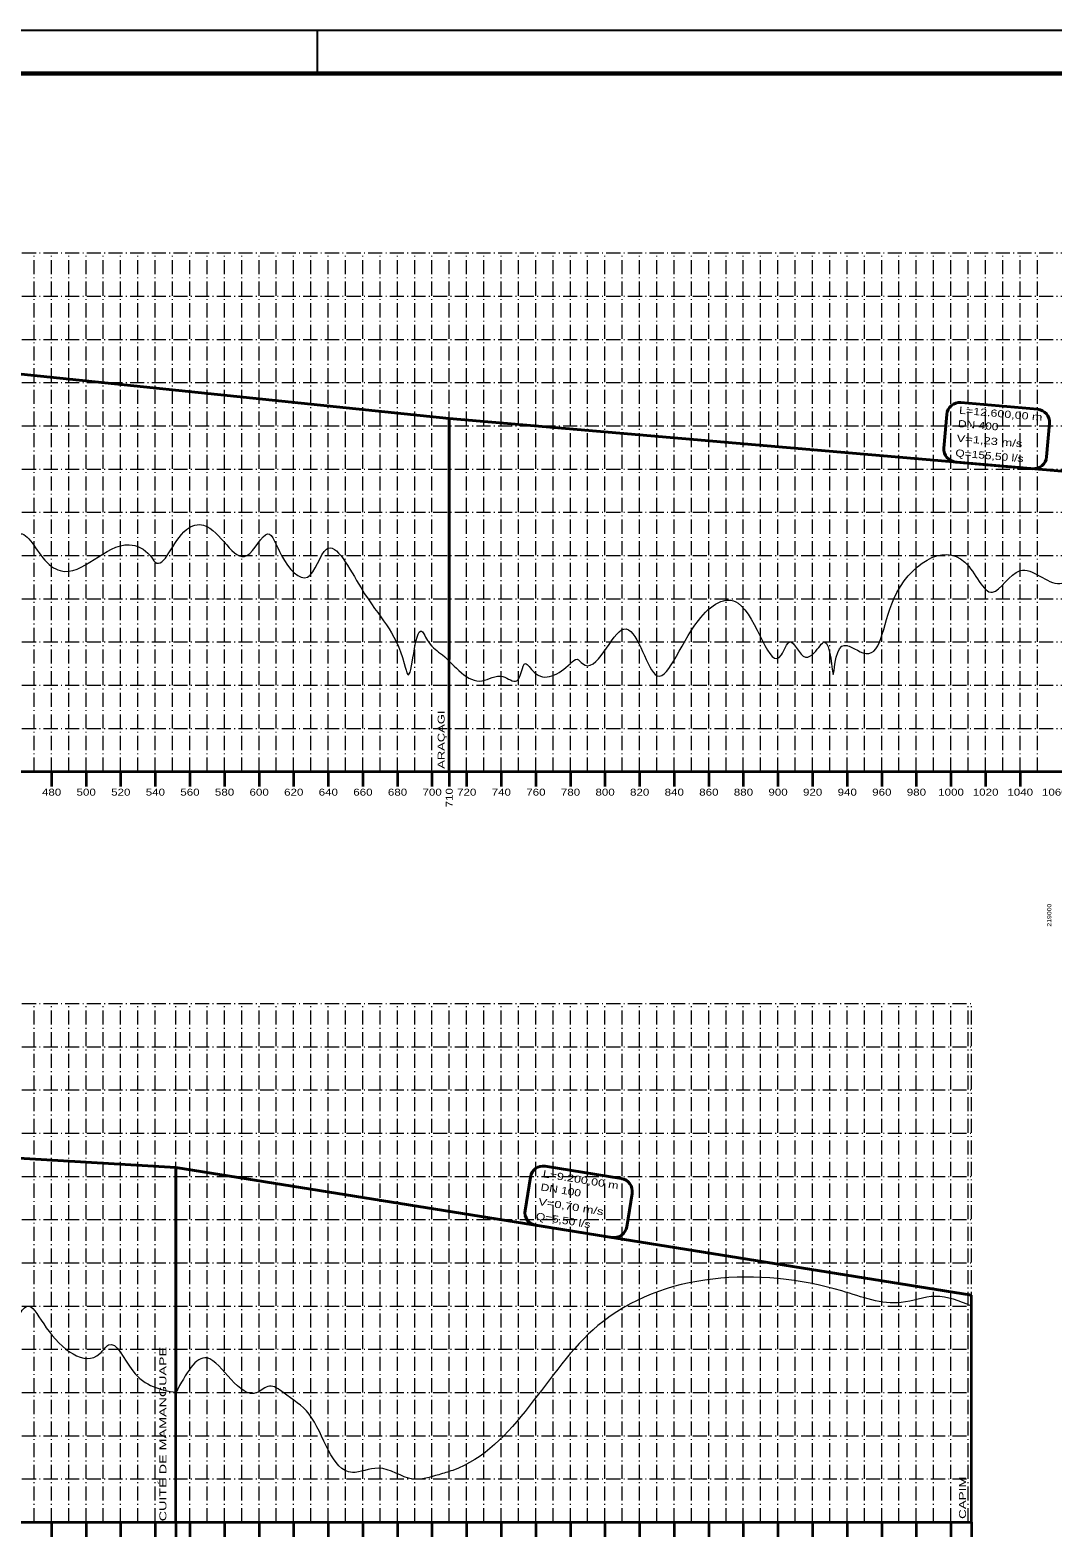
# Model space of a CAD drawing. Extents: x 0 to 1682, y 0 to 1188.
# Drawn here: x 479 to 952, y 490 to 1188 of the extents above; entities that cross this region are included whole.
import ezdxf
from ezdxf.enums import TextEntityAlignment as Align

# ---------------------------------------------------------------- set-up
doc = ezdxf.new("R2010")
doc.units = 0
doc.header["$LTSCALE"] = 1.3
doc.linetypes.add('DOT_DASHED', pattern=[7.7, 5, -1.2, 0.3, -1.2])
for name, color, linetype, lineweight in [('1', 7, 'DOT_DASHED', 13), ('55', 7, 'Continuous', 13), ('56', 7, 'Continuous', 13), ('62', 7, 'Continuous', 13), ('63', 7, 'Continuous', 25), ('9', 7, 'Continuous', 40)]:
    doc.layers.add(name, color=color, linetype=linetype, lineweight=lineweight)
doc.layers.add('24', color=7, linetype='Continuous')

msp = doc.modelspace()

# ---------------------------------------------------------------- linework, layer by layer
at = {"layer": '1'}
for p, q in [((104.775, 1084.796), (1296.775, 1084.796)), ((480.775, 844.796), (480.775, 1084.796)), ((488.775, 844.796), (488.775, 1084.796)), ((496.775, 844.796), (496.775, 1084.796)), ((504.775, 844.796), (504.775, 1084.796)), ((512.775, 844.796), (512.775, 1084.796)), ((520.775, 844.796), (520.775, 1084.796)), ((528.775, 844.796), (528.775, 1084.796)), ((536.775, 844.796), (536.775, 1084.796)), ((544.775, 844.796), (544.775, 1084.796)), ((552.775, 844.796), (552.775, 1084.796)), ((560.775, 844.796), (560.775, 1084.796)), ((568.775, 844.796), (568.775, 1084.796)), ((576.775, 844.796), (576.775, 1084.796)), ((584.775, 844.796), (584.775, 1084.796)), ((592.775, 844.796), (592.775, 1084.796)), ((600.775, 844.796), (600.775, 1084.796)), ((608.775, 844.796), (608.775, 1084.796)), ((616.775, 844.796), (616.775, 1084.796)), ((624.775, 844.796), (624.775, 1084.796)), ((632.775, 844.796), (632.775, 1084.796)), ((640.775, 844.796), (640.775, 1084.796)), ((648.775, 844.796), (648.775, 1084.796)), ((656.775, 844.796), (656.775, 1084.796)), ((664.775, 844.796), (664.775, 1084.796)), ((672.775, 844.796), (672.775, 1084.796)), ((680.775, 844.796), (680.775, 1084.796)), ((688.775, 844.796), (688.775, 1084.796)), ((696.775, 844.796), (696.775, 1084.796)), ((704.775, 844.796), (704.775, 1084.796)), ((712.775, 844.796), (712.775, 1084.796)), ((720.775, 844.796), (720.775, 1084.796)), ((728.775, 844.796), (728.775, 1084.796)), ((736.775, 844.796), (736.775, 1084.796)), ((744.775, 844.796), (744.775, 1084.796)), ((752.775, 844.796), (752.775, 1084.796)), ((760.775, 844.796), (760.775, 1084.796)), ((768.775, 844.796), (768.775, 1084.796)), ((776.775, 844.796), (776.775, 1084.796)), ((784.775, 844.796), (784.775, 1084.796)), ((792.775, 844.796), (792.775, 1084.796)), ((800.775, 844.796), (800.775, 1084.796)), ((808.775, 844.796), (808.775, 1084.796)), ((816.775, 844.796), (816.775, 1084.796)), ((824.775, 844.796), (824.775, 1084.796)), ((832.775, 844.796), (832.775, 1084.796)), ((840.775, 844.796), (840.775, 1084.796)), ((848.775, 844.796), (848.775, 1084.796)), ((856.775, 844.796), (856.775, 1084.796)), ((864.775, 844.796), (864.775, 1084.796)), ((872.775, 844.796), (872.775, 1084.796)), ((880.775, 844.796), (880.775, 1084.796)), ((888.775, 844.796), (888.775, 1084.796)), ((896.775, 844.796), (896.775, 1084.796)), ((904.775, 844.796), (904.775, 1084.796)), ((912.775, 844.796), (912.775, 1084.796)), ((920.775, 844.796), (920.775, 1084.796)), ((928.775, 844.796), (928.775, 1084.796)), ((936.775, 844.796), (936.775, 1084.796)), ((944.775, 844.796), (944.775, 1084.796)), ((104.775, 1064.796), (1296.775, 1064.796)), ((104.775, 1044.796), (1296.775, 1044.796)), ((104.775, 1024.796), (1296.775, 1024.796)), ((104.775, 1004.796), (1296.775, 1004.796)), ((104.775, 984.796), (1296.775, 984.796)), ((104.775, 964.796), (1296.775, 964.796)), ((104.775, 944.796), (1296.775, 944.796)), ((104.775, 924.796), (1296.775, 924.796)), ((104.775, 904.796), (1296.775, 904.796)), ((104.775, 884.796), (1296.775, 884.796)), ((104.775, 864.796), (1296.775, 864.796)), ((104.775, 737.538), (914.356, 737.538)), ((480.775, 497.538), (480.775, 737.538)), ((488.775, 497.538), (488.775, 737.538)), ((496.775, 497.538), (496.775, 737.538)), ((504.775, 497.538), (504.775, 737.538)), ((512.775, 497.538), (512.775, 737.538)), ((520.775, 497.538), (520.775, 737.538)), ((528.775, 497.538), (528.775, 737.538)), ((536.775, 497.538), (536.775, 737.538)), ((546.375, 497.538), (546.375, 737.538)), ((552.775, 497.538), (552.775, 737.538)), ((560.775, 497.538), (560.775, 737.538)), ((568.775, 497.538), (568.775, 737.538)), ((576.775, 497.538), (576.775, 737.538)), ((584.775, 497.538), (584.775, 737.538)), ((592.775, 497.538), (592.775, 737.538)), ((600.775, 497.538), (600.775, 737.538)), ((608.775, 497.538), (608.775, 737.538)), ((616.775, 497.538), (616.775, 737.538)), ((624.775, 497.538), (624.775, 737.538)), ((632.775, 497.538), (632.775, 737.538)), ((640.775, 497.538), (640.775, 737.538)), ((648.775, 497.538), (648.775, 737.538)), ((656.775, 497.538), (656.775, 737.538)), ((664.775, 497.538), (664.775, 737.538)), ((672.775, 497.538), (672.775, 737.538)), ((680.775, 497.538), (680.775, 737.538)), ((688.775, 497.538), (688.775, 737.538)), ((696.775, 497.538), (696.775, 737.538)), ((704.775, 497.538), (704.775, 737.538)), ((712.775, 497.538), (712.775, 737.538)), ((720.775, 497.538), (720.775, 737.538)), ((728.775, 497.538), (728.775, 737.538)), ((736.775, 497.538), (736.775, 737.538)), ((744.775, 497.538), (744.775, 737.538)), ((752.775, 497.538), (752.775, 737.538)), ((760.775, 497.538), (760.775, 737.538)), ((768.775, 497.538), (768.775, 737.538)), ((776.775, 497.538), (776.775, 737.538)), ((784.775, 497.538), (784.775, 737.538)), ((792.775, 497.538), (792.775, 737.538)), ((800.775, 497.538), (800.775, 737.538)), ((808.775, 497.538), (808.775, 737.538)), ((816.775, 497.538), (816.775, 737.538)), ((824.775, 497.538), (824.775, 737.538)), ((832.775, 497.538), (832.775, 737.538)), ((840.775, 497.538), (840.775, 737.538)), ((848.775, 497.538), (848.775, 737.538)), ((856.775, 497.538), (856.775, 737.538)), ((864.775, 497.538), (864.775, 737.538)), ((872.775, 497.538), (872.775, 737.538)), ((880.775, 497.538), (880.775, 737.538)), ((888.775, 497.538), (888.775, 737.538)), ((896.775, 497.538), (896.775, 737.538)), ((904.775, 497.538), (904.775, 737.538)), ((912.775, 497.538), (912.775, 737.538)), ((914.356, 497.538), (914.356, 737.538)), ((104.775, 717.538), (914.356, 717.538)), ((104.775, 697.538), (914.356, 697.538)), ((104.775, 677.538), (914.356, 677.538)), ((104.775, 657.538), (914.356, 657.538)), ((104.775, 637.538), (914.356, 637.538)), ((104.775, 617.538), (914.356, 617.538)), ((104.775, 597.538), (914.356, 597.538)), ((104.775, 577.538), (914.356, 577.538)), ((104.775, 557.538), (914.356, 557.538)), ((104.775, 537.538), (914.356, 537.538)), ((104.775, 517.538), (914.356, 517.538))]:
    msp.add_line(p, q, dxfattribs=at)
at = {"layer": '55'}
msp.add_spline([(104.775, 889.796), (114.375, 884.796), (116.375, 879.796), (118.375, 884.796), (119.975, 894.796), (121.575, 884.796), (123.175, 894.796), (132.775, 917.796), (136.775, 904.796), (139.175, 889.796), (149.575, 922.796), (165.575, 914.796), (186.375, 873.796), (227.175, 913.796), (235.175, 904.796), (242.375, 914.796), (258.375, 918.796), (266.375, 922.796), (287.975, 922.796), (300.775, 914.796), (308.775, 894.796), (310.375, 899.796), (311.975, 894.796), (328.775, 879.796), (343.175, 904.796), (367.975, 926.796), (388.775, 924.796), (402.375, 927.796), (434.375, 931.796), (442.375, 925.796), (475.175, 954.796), (488.775, 939.796), (492.775, 937.796), (524.775, 949.796), (534.375, 944.796), (536.775, 941.796), (551.175, 956.796), (559.175, 958.796), (579.175, 944.796), (588.775, 954.796), (595.175, 944.796), (607.175, 934.796), (615.975, 947.796), (631.975, 929.796), (651.975, 894.796), (653.575, 889.796), (659.975, 909.796), (663.175, 904.796), (669.575, 898.796), (687.975, 886.796), (697.575, 888.796), (703.975, 886.796), (707.975, 894.796), (711.975, 890.796), (728.775, 894.796), (731.975, 896.796), (734.375, 894.796), (753.575, 910.796), (767.975, 889.796), (787.975, 914.796), (806.375, 922.796), (826.375, 898.796), (830.375, 904.796), (837.575, 897.796), (841.575, 899.796), (846.375, 904.796), (850.375, 889.796), (854.375, 902.796), (863.975, 899.796), (878.375, 924.796), (911.175, 941.796), (923.975, 927.796), (936.775, 937.796), (955.175, 931.796), (969.575, 939.796), (1002.375, 919.796), (1022.375, 939.796), (1070.375, 954.796), (1088.775, 937.796), (1096.775, 944.796), (1103.975, 938.796), (1124.775, 959.796), (1148.775, 940.796), (1153.575, 944.796), (1156.775, 937.796), (1166.644, 960.143), (1170.611, 963.809), (1176.775, 959.796)], degree=3, dxfattribs=at)
at = {"layer": '56'}
for points in [[(914.356, 597.538), (897.533, 602.013), (881.846, 599.164), (854.352, 604.513), (741.552, 588.513), (674.352, 521.513), (667.952, 519.513), (655.952, 517.513), (639.952, 522.513), (627.952, 520.513), (607.952, 547.513), (595.952, 557.513), (589.552, 560.513), (583.952, 557.513), (560.752, 573.513), (546.352, 557.513)], [(451.175, 590.538), (463.175, 569.538), (478.375, 597.538), (486.375, 587.538), (511.175, 575.538), (515.175, 579.538), (526.375, 567.538), (546.375, 557.538)]]:
    msp.add_spline(points, degree=3, dxfattribs=at)
at = {"layer": '62', "lineweight": 35}
for p, q in [((672.775, 844.796), (672.775, 896.709)), ((488.775, 844.796), (488.775, 837.968)), ((504.775, 844.796), (504.775, 837.968)), ((520.775, 844.796), (520.775, 837.968)), ((536.775, 844.796), (536.775, 837.968)), ((552.775, 844.796), (552.775, 837.968)), ((568.775, 844.796), (568.775, 837.968)), ((584.775, 844.796), (584.775, 837.968)), ((600.775, 844.796), (600.775, 837.968)), ((616.775, 844.796), (616.775, 837.968)), ((632.775, 844.796), (632.775, 837.968)), ((648.775, 844.796), (648.775, 837.968)), ((664.775, 844.796), (664.775, 837.968)), ((672.775, 844.796), (672.775, 837.968)), ((680.775, 844.796), (680.775, 837.968)), ((696.775, 844.796), (696.775, 837.968)), ((712.775, 844.796), (712.775, 837.968)), ((728.775, 844.796), (728.775, 837.968)), ((744.775, 844.796), (744.775, 837.968)), ((760.775, 844.796), (760.775, 837.968)), ((776.775, 844.796), (776.775, 837.968)), ((792.775, 844.796), (792.775, 837.968)), ((808.775, 844.796), (808.775, 837.968)), ((824.775, 844.796), (824.775, 837.968)), ((840.775, 844.796), (840.775, 837.968)), ((856.775, 844.796), (856.775, 837.968)), ((872.775, 844.796), (872.775, 837.968)), ((888.775, 844.796), (888.775, 837.968)), ((904.775, 844.796), (904.775, 837.968)), ((920.775, 844.796), (920.775, 837.968)), ((936.775, 844.796), (936.775, 837.968)), ((914.356, 497.538), (914.356, 602.538)), ((546.375, 497.538), (546.375, 557.538)), ((104.775, 497.538), (914.356, 497.538)), ((488.775, 497.538), (488.775, 490.71)), ((504.775, 497.538), (504.775, 490.71)), ((520.775, 497.538), (520.775, 490.71)), ((536.775, 497.538), (536.775, 490.71)), ((546.375, 497.538), (546.375, 490.71)), ((552.775, 497.538), (552.775, 490.71)), ((568.775, 497.538), (568.775, 490.71)), ((584.775, 497.538), (584.775, 490.71)), ((600.775, 497.538), (600.775, 490.71)), ((616.775, 497.538), (616.775, 490.71)), ((632.775, 497.538), (632.775, 490.71)), ((648.775, 497.538), (648.775, 490.71)), ((664.775, 497.538), (664.775, 490.71)), ((680.775, 497.538), (680.775, 490.71)), ((696.775, 497.538), (696.775, 490.71)), ((712.775, 497.538), (712.775, 490.71)), ((728.775, 497.538), (728.775, 490.71)), ((744.775, 497.538), (744.775, 490.71)), ((760.775, 497.538), (760.775, 490.71)), ((776.775, 497.538), (776.775, 490.71)), ((792.775, 497.538), (792.775, 490.71)), ((808.775, 497.538), (808.775, 490.71)), ((824.775, 497.538), (824.775, 490.71)), ((840.775, 497.538), (840.775, 490.71)), ((856.775, 497.538), (856.775, 490.71)), ((872.775, 497.538), (872.775, 490.71)), ((888.775, 497.538), (888.775, 490.71)), ((904.775, 497.538), (904.775, 490.71)), ((914.356, 497.538), (914.356, 490.71))]:
    msp.add_line(p, q, dxfattribs=at)
msp.add_lwpolyline([(104.775, 844.796), (384.775, 844.796), (1176.775, 844.796)], dxfattribs=at)
at = {"layer": '63'}
for p, q in [((-0.168, 1187.881), (1681.832, 1187.881)), ((611.832, 1167.881), (611.832, 1187.881))]:
    msp.add_line(p, q, dxfattribs=at)
at = {"layer": '63', "lineweight": 60}
msp.add_lwpolyline([(49.832, 1167.881), (1661.832, 1167.881), (1661.832, 19.881), (1311.832, 19.881)], dxfattribs=at)
at = {"layer": '9'}
for p, q in [((909.394, 1015.549), (944.896, 1012.49)), ((672.775, 896.709), (672.775, 1008.226)), ((902.901, 1010.086), (901.561, 994.533)), ((950.359, 1005.997), (949.019, 990.444)), ((907.024, 988.04), (942.526, 984.981)), ((546.375, 557.538), (546.375, 661.698)), ((710.281, 657.235), (707.803, 641.822)), ((717.157, 662.206), (752.339, 656.55)), ((757.311, 649.674), (754.833, 634.261)), ((712.774, 634.946), (747.957, 629.29))]:
    msp.add_line(p, q, dxfattribs=at)
for points in [[(104.775, 1070.086), (148.775, 1062.526), (672.775, 1008.226), (1176.775, 964.796)], [(104.775, 687.838), (546.375, 661.698), (914.356, 602.538)]]:
    msp.add_lwpolyline(points, dxfattribs=at)
for centre, start, end in [((908.879, 1009.571), 85.07494, 175.07494), ((944.381, 1006.512), 355.07494, 85.07494), ((907.539, 994.018), 175.07494, 265.07494), ((943.041, 990.959), 265.07494, 355.07494), ((716.205, 656.282), 80.86677, 170.86677), ((751.387, 650.626), 350.86677, 80.86677), ((713.727, 640.87), 170.86677, 260.86677), ((748.909, 635.213), 260.86677, 350.86677)]:
    msp.add_arc(centre, 6, start, end, dxfattribs=at)

# ---------------------------------------------------------------- texts
at = {"layer": '24'}
for s, width, p in [('ARAÇAGI', 1.4, (670.614, 846.113)), ('CUITÉ DE MAMANGUAPE', 1.55, (541.921, 497.945)), ('CAPIM', 1.45, (911.765, 499.06))]:
    msp.add_text(s, height=3.2, rotation=90, dxfattribs=dict(at, width=width)).set_placement(p)
at = {"layer": '24', "width": 1.25}
for s, p in [('480', (488.84, 833.708)), ('500', (504.84, 833.708)), ('520', (520.84, 833.708)), ('540', (536.84, 833.708)), ('560', (552.84, 833.708)), ('580', (568.84, 833.708)), ('600', (584.84, 833.708)), ('620', (600.84, 833.708)), ('640', (616.84, 833.708)), ('660', (632.84, 833.708)), ('680', (648.84, 833.708)), ('700', (664.84, 833.708)), ('720', (680.84, 833.708)), ('740', (696.84, 833.708)), ('760', (712.84, 833.708)), ('780', (728.84, 833.708)), ('800', (744.84, 833.708)), ('820', (760.84, 833.708)), ('840', (776.84, 833.708)), ('860', (792.84, 833.708)), ('880', (808.84, 833.708)), ('900', (824.84, 833.708)), ('920', (840.84, 833.708)), ('940', (856.84, 833.708)), ('960', (872.84, 833.708)), ('980', (888.84, 833.708)), ('1000', (904.84, 833.708)), ('1020', (920.84, 833.708)), ('1040', (936.84, 833.708)), ('1060', (952.84, 833.708))]:
    msp.add_text(s, height=3.2, dxfattribs=at).set_placement(p, align=Align.CENTER)
msp.add_text('710', height=3.2, rotation=90, dxfattribs=at).set_placement((674.346, 832.733), align=Align.CENTER)
at = {"layer": '63', "width": 1.25}
msp.add_text('219000', height=1.911, rotation=90, dxfattribs=at).set_placement((951.203, 773.077))
at = {"layer": '9'}
for s, rotation, width, p in [('L=12.600,00 m', 355.075, 1.3, (908.436, 1010.434)), ('DN 400', 355.075, 1.25, (907.905, 1004.277)), ('V=1,23 m/s', 355.075, 1.35, (907.32, 997.478)), ('Q=155,50 l/s', 355.075, 1.25, (906.734, 990.68)), ('L=9.200,00 m', 350.867, 1.3, (715.826, 657.175)), ('DN 100', 350.867, 1.25, (714.845, 651.074)), ('V=0,70 m/s', 350.867, 1.35, (713.762, 644.337)), ('Q=5,50 l/s', 350.867, 1.25, (712.679, 637.599))]:
    msp.add_text(s, height=3.319, rotation=rotation, dxfattribs=dict(at, width=width)).set_placement(p)

doc.saveas('drawing.dxf')
